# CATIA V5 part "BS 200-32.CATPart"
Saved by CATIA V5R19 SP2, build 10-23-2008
Part number: BS 200-32
Bounding box of the stored display mesh (mm): x -12.497 to 12.497, y -12.358 to 12.358, z 0 to 94
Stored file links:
  C:\Users\Bora\Desktop\3D Katı model\BS serisi\BS 200\BS 200-32.CATPart
  C:\Program Files\Dassault Systemes\B19\intel_a\reffiles\standard\MetricThickPitch.txt
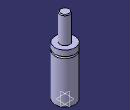
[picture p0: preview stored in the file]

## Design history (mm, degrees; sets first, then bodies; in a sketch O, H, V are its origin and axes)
Body1 (main body)
  Sketch1 on yz-plane, origin (0, 0, 0), H (0, 1, 0), V (0, 0, 1)
    point P1 (6, 93)
    point P3 (6, 93)
    point P5 (12.5, 54)
    point P6 (12.5, 52)
    point P8 (12.5, 52)
    point P9 (12.5, 54)
    line L1 (6, 93) -> (6, 61)
    arc A1 centre (5, 93) radius 1 from (6, 93) to (5, 94) ccw
    arc A2 centre (12.5, 53) radius 1 from (12.5, 54) to (12.5, 52) ccw
    line L2 (12.5, 0) -> (12.5, 52)
    line L3 (12.5, 54) -> (12.5, 61)
    line L4 (5, 94) -> (0, 94)
    point P11 (0, 94)
    line L5 (6, 61) -> (12.5, 61)
    line L6 (12.5, 0) -> (0, 0)
    coincidence: P11 V, P1 P3, P5 P9, P6 P8
    tangency: L4 A1
    horizontal: L5 H, L6 H
  Shaft1: profile Sketch1, axis Sketch1.V, angle 360
  Sketch2 on face of Shaft1 from Sketch1.L6, origin (0, 0, 0), H (1, 0, 0), V (0, -1, 0)
    point P1 (0, 0)
  Hole1: placed by Sketch2, at (0, 0, 0) direction (0, 0, 1), diameter 4.917, depth 4, threaded "M6", thread diameter 6, thread depth 4, pitch 1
